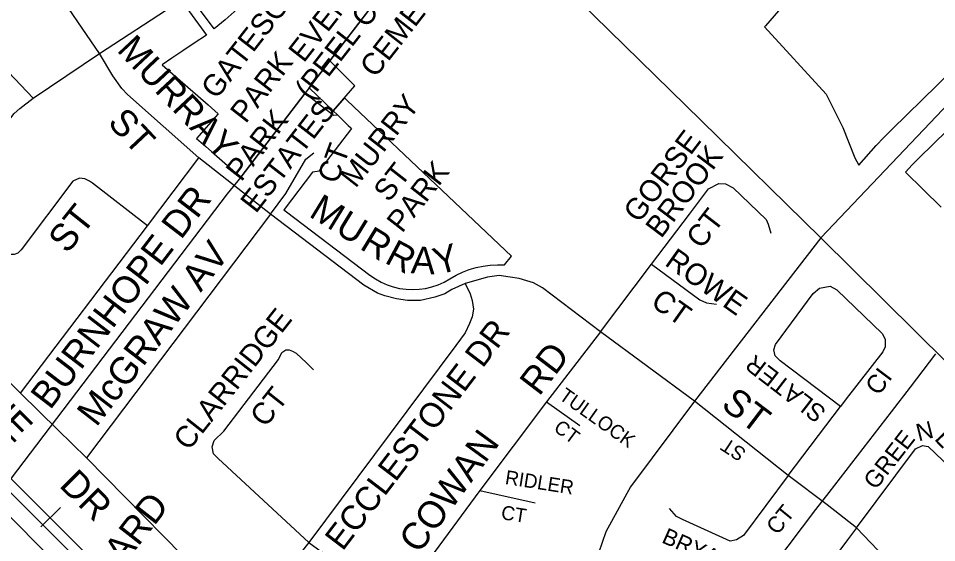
# Model space of a CAD drawing. Extents: x 586326 to 623965, y 4819854 to 4857850.
# Drawn here: x 597777 to 598626, y 4838866 to 4839351 of the extents above; entities that cross this region are included whole.
import ezdxf

# ---------------------------------------------------------------- set-up
doc = ezdxf.new("R2010")
doc.units = 0
for name, color, linetype in [('Cemeteries', 7, 'Continuous'), ('Lots_Concessions', 7, 'Continuous'), ('Major Rds and Hwys', 7, 'Continuous'), ('Minor Rd Lbls', 7, 'Continuous'), ('Minor Rds', 7, 'Continuous'), ('Park Lbls', 7, 'Continuous'), ('Park Outlines', 7, 'Continuous'), ('Private Rd Lbls', 7, 'Continuous'), ('Private Rds', 7, 'Continuous'), ('Railways_lbls', 7, 'Continuous'), ('School Syms_Lbls', 7, 'Continuous')]:
    doc.layers.add(name, color=color, linetype=linetype)

msp = doc.modelspace()

# ---------------------------------------------------------------- linework, layer by layer
at = {"layer": 'Cemeteries'}
for p, q in [((598064.76, 4839311.52), (598045.74, 4839286.64)), ((598088.08, 4839288.56), (598064.76, 4839311.52)), ((598045.74, 4839286.64), (598067.9, 4839265.31)), ((598067.9, 4839265.31), (598088.08, 4839288.56))]:
    msp.add_line(p, q, dxfattribs=at)
at = {"layer": 'Lots_Concessions'}
for p, q in [((598118.48, 4839381.78), (598064.76, 4839311.52)), ((598064.76, 4839311.52), (598045.74, 4839286.64)), ((598045.74, 4839286.64), (597982.55, 4839203.92)), ((597982.55, 4839203.92), (597969.9, 4839188.43)), ((597969.9, 4839188.43), (597343.34, 4838363.94)), ((598601.96, 4839009.58), (598625.68, 4839040.4)), ((598584.38, 4838986.73), (598601.96, 4839009.58)), ((598526.83, 4838911.95), (598584.38, 4838986.73)), ((598514.63, 4838896.1), (598526.83, 4838911.95)), ((598413.22, 4838763.17), (598514.63, 4838896.1))]:
    msp.add_line(p, q, dxfattribs=at)
at = {"layer": 'Major Rds and Hwys'}
for points in [[(598519.26, 4839147.74), (598744.92, 4839385.74)], [(598408.44, 4839256.27), (598294.8, 4839367.57)], [(598519.26, 4839147.74), (598408.44, 4839256.27)], [(598519.26, 4839147.74), (598402.28, 4838996.68)], [(598801.26, 4838868.41), (598752.51, 4838916.7), (598519.26, 4839147.74)], [(598402.28, 4838996.68), (598343.13, 4838917.33), (598320.28, 4838875.46), (598296.55, 4838806.27)]]:
    msp.add_lwpolyline(points, dxfattribs=at)
at = {"layer": 'Minor Rds'}
for points in [[(597851.74, 4839318.45), (597806.99, 4839384.12), (597804.3, 4839390.42), (597797.5, 4839404.46), (597796.33, 4839411.08), (597795.19, 4839418.56), (597794.53, 4839425.02), (597792.61, 4839459.92), (597791.26, 4839482.53)], [(597851.74, 4839318.45), (597919.78, 4839362.93)], [(597778.54, 4839003.97), (597611.83, 4839170.11), (597608.79, 4839180.39), (597613.35, 4839189.52), (597724.51, 4839331.52), (597731.37, 4839334.18), (597738.6, 4839331.52), (597790.16, 4839277.1)], [(597790.16, 4839277.1), (597851.74, 4839318.45)], [(597943.65, 4839221.99), (597877.61, 4839280.4), (597872.39, 4839285.91), (597863.98, 4839297.88), (597851.74, 4839318.45)], [(597896.23, 4839158.86), (597845.36, 4839198.52), (597842.34, 4839200.33), (597838.17, 4839202.32), (597833.05, 4839203.07), (597826.92, 4839200.18), (597779.14, 4839136.66), (597776.2, 4839133.67), (597772.71, 4839132.33), (597768.04, 4839132.33), (597763.25, 4839134.25), (597747.78, 4839149.79), (597724.82, 4839171.58), (597717.61, 4839179.24), (597717.13, 4839182.26), (597716.98, 4839186.23), (597717.89, 4839189.99), (597720.73, 4839194.67), (597772.64, 4839262.92), (597777.88, 4839267.55), (597790.16, 4839277.1)], [(597896.23, 4839158.86), (597943.65, 4839221.99)], [(598010.03, 4839169.73), (597943.65, 4839221.99)], [(598397.55, 4839169.62), (598415.33, 4839193.03), (598424.65, 4839198.01), (598430.93, 4839197.8), (598437.87, 4839194.11), (598468.59, 4839164.73), (598470.32, 4839160.57), (598472.81, 4839152.13)], [(598010.03, 4839169.73), (597839.72, 4838944.05)], [(598190.12, 4839105.41), (598177.69, 4839100.05), (598171.37, 4839096.02), (598161.95, 4839092.91), (598148.75, 4839089.82), (598136.69, 4839089.81), (598126.44, 4839091.31), (598115.79, 4839093.92), (598108.97, 4839096.56), (598096.23, 4839103.81), (598010.03, 4839169.73)], [(598362.52, 4839123.48), (598397.55, 4839169.62)], [(597778.54, 4839003.97), (597896.23, 4839158.86)], [(598315.41, 4839060.84), (598362.52, 4839123.48)], [(598362.52, 4839123.48), (598407.06, 4839090.4), (598413.24, 4839087.52), (598422.6, 4839086.48)], [(598315.41, 4839060.84), (598261.57, 4839101.34), (598253.37, 4839105.96), (598247.22, 4839108.01), (598240.08, 4839110.07), (598231.6, 4839111.39), (598221.35, 4839112.89), (598210.63, 4839111.35), (598190.12, 4839105.41)], [(598190.12, 4839105.41), (598194.68, 4839095.81), (598196.39, 4839089.88), (598197.69, 4839081.8), (598196.45, 4839074.53), (598194.14, 4839068.32), (598190.14, 4839059.95), (598181.49, 4839048.07), (598045.46, 4838865.69)], [(598537.46, 4838991.6), (598481.63, 4839033.92), (598476.96, 4839038.61), (598475.75, 4839044.2), (598477.22, 4839048.9), (598512.18, 4839096.28), (598518.01, 4839101.13), (598527.86, 4839103.08), (598533.82, 4839099.75), (598575.85, 4839059.11), (598578.76, 4839053.98), (598578.76, 4839046.77), (598576.46, 4839042.18)], [(598315.41, 4839060.84), (598265.27, 4838995.88)], [(598402.28, 4838996.68), (598315.41, 4839060.84)], [(598045.46, 4838865.69), (597961.34, 4838943.34), (597957.05, 4838947.82), (597955.79, 4838954.11), (597957.88, 4838959.97), (597966.68, 4838968.77), (598017.39, 4839034.98), (598020.3, 4839041.54), (598024.14, 4839044.02), (598027.3, 4839044.01), (598030.24, 4839042.9), (598033.78, 4839040.93), (598043.25, 4839031.94), (598049.62, 4839025.46)], [(598576.46, 4839042.18), (598542.66, 4838998.54), (598537.46, 4838991.6)], [(597839.72, 4838944.05), (597813.1, 4838970.12), (597778.54, 4839003.97)], [(598488.81, 4838927.77), (598402.28, 4838996.68)], [(598265.27, 4838995.88), (598203.63, 4838913.67)], [(598265.27, 4838995.88), (598296.16, 4838973.94)], [(598488.81, 4838927.77), (598537.46, 4838991.6)], [(598552.12, 4838879.27), (598606.82, 4838952.51), (598613.24, 4838955.36), (598618.59, 4838954.58), (598693.68, 4838882.58), (598697.88, 4838875.33), (598697.46, 4838868.21), (598637.78, 4838789.42)], [(598045.46, 4838865.69), (597995.64, 4838802.88), (597992.81, 4838800.89), (597985.33, 4838799.44), (597981.81, 4838799.81), (597975.98, 4838804.52), (597972.14, 4838809.35), (597963.92, 4838817.51), (597839.72, 4838944.05)], [(598488.81, 4838927.77), (598447.43, 4838872.03), (598441.19, 4838868.13), (598435.19, 4838866.83), (598391.09, 4838886.88), (598385.67, 4838889.67), (598379.1, 4838897.3)], [(598552.12, 4838879.27), (598524.88, 4838900.41), (598488.81, 4838927.77)], [(598203.63, 4838913.67), (598127.66, 4838810.74)], [(598203.63, 4838913.67), (598254.78, 4838902.29)], [(598552.12, 4838879.27), (598543.9, 4838868.22), (598505.68, 4838816.83)], [(598637.78, 4838789.42), (598552.12, 4838879.27)], [(598045.46, 4838865.69), (598084.16, 4838837.27), (598127.66, 4838810.74)]]:
    msp.add_lwpolyline(points, dxfattribs=at)
at = {"layer": 'Park Outlines'}
for points in [[(598515.61, 4839399.54), (598468.06, 4839344.18), (598467.07, 4839343.02), (598524, 4839280.92), (598539.61, 4839249.94), (598550.6, 4839221.98), (598554.16, 4839215.13), (598570.34, 4839233.14), (598577.4, 4839240.74), (598584.69, 4839248.11), (598682.89, 4839344.13)], [(597932.45, 4839360.28), (597950.64, 4839335.39), (597939.36, 4839327.88), (597928.87, 4839320.9), (597918.47, 4839313.98), (597909.75, 4839307.95), (597914.52, 4839303.78), (597923.93, 4839295.57), (597933.35, 4839287.35), (597942.76, 4839279.13), (597952.18, 4839270.91), (597961.59, 4839262.69), (597941.54, 4839239.72), (597949.97, 4839232.36), (597955.25, 4839227.75), (597982.55, 4839203.92), (597982.74, 4839204.16), (598042.1, 4839281.87), (598068.08, 4839261.35), (598071.84, 4839261.52), (598067.9, 4839265.31), (598045.74, 4839286.64), (598064.77, 4839311.54), (598118.48, 4839381.78)], [(597979.09, 4839359.45), (597967.93, 4839349.54), (597957.7, 4839341.17), (597939.7, 4839365.8)], [(598687.88, 4839297.87), (598610.26, 4839221.97), (598603.79, 4839215.44), (598597.54, 4839208.7), (598613.98, 4839192.43), (598630.51, 4839176.21)], [(597872.48, 4838808.99), (597631.54, 4839049.97)], [(597726.51, 4838931.75), (597842.77, 4838815.48)]]:
    msp.add_lwpolyline(points, dxfattribs=at)
for points in [[(598078.42, 4839277.39), (598067.9, 4839265.31), (598071.84, 4839261.52), (598081.84, 4839251.9), (598084.01, 4839249.8), (598084.74, 4839249.11), (598054.68, 4839209.59), (598053.22, 4839209.31), (598048.81, 4839208.48), (598022.52, 4839173.9), (598022.34, 4839173.66), (598024.73, 4839171.85), (598101.96, 4839113.11), (598106.94, 4839109.67), (598112.22, 4839106.72), (598117.75, 4839104.26), (598123.48, 4839102.34), (598129.38, 4839100.95), (598135.37, 4839100.12), (598141.41, 4839099.85), (598147.46, 4839100.14), (598153.45, 4839100.99), (598159.33, 4839102.4), (598165.06, 4839104.35), (598170.59, 4839106.82), (598175.85, 4839109.8), (598181.61, 4839113.11), (598187.61, 4839115.96), (598193.81, 4839118.33), (598200.17, 4839120.21), (598206.67, 4839121.59), (598213.25, 4839122.46), (598219.88, 4839122.81), (598226.51, 4839122.64), (598232.8, 4839130.9), (598092.91, 4839263.64), (598080.59, 4839275.33)], [(597726.51, 4838931.75), (597724.17, 4838928.82), (597667.1, 4838857.32), (597595.11, 4838767.14), (597620.74, 4838739.25), (597627.16, 4838732.55), (597710.25, 4838649.46), (597840.08, 4838812.12), (597842.77, 4838815.48), (597726.51, 4838931.75)]]:
    msp.add_lwpolyline(points, close=True, dxfattribs=at)
at = {"layer": 'Private Rds'}
msp.add_lwpolyline([(598010.03, 4839169.73), (598024.1, 4839188.74), (598042.46, 4839220.55), (598049.91, 4839226.55)], dxfattribs=at)
at = {"layer": 'Railways_lbls'}
msp.add_line((597815.48, 4838898.1), (597797.48, 4838880.1), dxfattribs=at)
msp.add_lwpolyline([(597998.97, 4838694.27), (597829.48, 4838865.1), (597828.48, 4838866.1), (597641.48, 4839053.1)], dxfattribs=at)

# ---------------------------------------------------------------- texts
at = {"layer": 'Cemeteries'}
for s, p in [('(PEEL CO. MANOR)', (598046.65, 4839274.35)), ('EVENTIDE', (598040.71, 4839309.08)), ('CEMETERY', (598106.83, 4839295.06))]:
    msp.add_text(s, height=20, rotation=52.00002, dxfattribs=at).set_placement(p)
at = {"layer": 'Minor Rd Lbls'}
for s, height, rotation, p in [('MURRAY', 24.504, 313.21011, (597866.93, 4839321.03)), ('ST', 24.504, 313.21011, (597858.34, 4839253.7)), ('GORSE', 19.998, 52.81062, (598350.91, 4839160.62)), ('BROOK', 19.998, 52.89689, (598371.39, 4839146.46)), ('BURNHOPE DR', 25.002, 52.48506, (597806.01, 4838987.68)), ('M', 25, 328.57045, (598044.48, 4839168.1)), ('ST', 25.002, 51.34021, (597821.93, 4839132.23)), ('CT', 19.998, 52.31694, (598408.78, 4839136.48)), ('U', 25, 328.57045, (598068.48, 4839153.1)), ('R', 25, 328.57045, (598091.48, 4839138.1)), ('McGRAW AV', 25.002, 52.29444, (597848.76, 4838971.88)), ('R', 25, 331.92753, (598114.48, 4839125.1)), ('Y', 25, 15.52413, (598164.48, 4839113.1)), ('ECCLESTONE      DR', 25.002, 315.03615, (597613.73, 4839117.39)), ('A', 25, 356.98723, (598139.48, 4839115.1)), ('ROWE', 19.998, 324.63756, (598373.72, 4839123.04)), ('CT', 19.998, 324.63756, (598360.63, 4839085.66)), ('CLARRIDGE', 19.998, 51.70994, (597934.2, 4838949.78)), ('ECCLESTONE DR', 22.5998, 52.59466, (598076.6, 4838856.96)), ('RD', 25.002, 52.54671, (598258.53, 4839000.39)), ('SLATER', 16.416, 142.32206, (598525.22, 4838988.32)), ('CI', 16.998, 53.03468, (598572.47, 4839000.75)), ('CT', 19.998, 51.62295, (598005.1, 4838971.32)), ('TULLOCK', 13.002, 324.63756, (598275.94, 4838999.05)), ('ST', 25.002, 322.75916, (598425.72, 4838991.09)), ('CT', 13.002, 323.42699, (598271.01, 4838969.83)), ('N', 16, 14.13451, (598609.61, 4838959.28)), ('LEAF', 16.998, 314.20701, (598623.48, 4838961.04)), ('COWAN', 25.002, 53.90103, (598147.27, 4838854.34)), ('GREE', 16.002, 52.06675, (598569.92, 4838913.62)), ('ST', 13.002, 146.76217, (598451.06, 4838950.86)), ('RIDLER', 13.002, 351.08509, (598226.41, 4838919.89)), ('CT', 13.002, 351.08509, (598222.68, 4838887.35)), ('CT', 15, 50.86951, (598478.95, 4838871.88)), ('BRYANT', 15, 336.10385, (598371.02, 4838865.97))]:
    msp.add_text(s, height=height, rotation=rotation, dxfattribs=at).set_placement(p)
at = {"layer": 'Park Lbls'}
for s, p in [('GATESGILL', (597959.85, 4839275.18)), ('PARK', (597986.9, 4839252.85)), ('MURRY', (598088.67, 4839193.07)), ('ST', (598119.48, 4839179.94)), ('PARK', (598131.65, 4839151.42))]:
    msp.add_text(s, height=19.992, rotation=52.00002, dxfattribs=at).set_placement(p)
at = {"layer": 'Private Rd Lbls'}
for s, rotation, p in [(' ESTATES', 52.16366, (597991.79, 4839163.72)), ('PARK ', 52.16366, (597982.84, 4839198.98)), ('CT', 70.01691, (598071.52, 4839196.81))]:
    msp.add_text(s, height=19.998, rotation=rotation, dxfattribs=at).set_placement(p)
at = {"layer": 'School Syms_Lbls'}
msp.add_text('ROYAL ORCHARD', height=25, rotation=52.00002, dxfattribs=at).set_placement((597737.55, 4838669.69))

doc.saveas('drawing.dxf')
